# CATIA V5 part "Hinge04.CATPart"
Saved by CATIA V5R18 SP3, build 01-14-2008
Part number: Hinge 04
Bounding box of the stored display mesh (mm): x -47.5 to 47.5, y -15 to 15, z -22 to 22
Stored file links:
  E:\#00 CATIA V5 Movie\#03 CATIA V5 Data\#07 KIN\Balance Unit (1)\Hinge04.CATPart
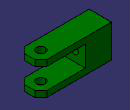
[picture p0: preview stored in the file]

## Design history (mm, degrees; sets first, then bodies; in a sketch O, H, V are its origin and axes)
Body1 (main body)
  Sketch1 on xy-plane, origin (0, 0, 0), H (1, 0, 0), V (0, 1, 0)
    line L1 (47.5, 7) -> (47.5, -7)
    line L2 (39.5, -15) -> (-47.5, -15)
    line L3 (-47.5, -15) -> (-47.5, 15)
    line L4 (-47.5, 15) -> (39.5, 15)
    point P1 (47.5, 15)
    point P2 (47.5, -15)
    point P4 (-47.5, 15)
    line L5 (47.5, 7) -> (39.5, 15)
    point P5 (47.5, 7)
    point P6 (39.5, 15)
    line L6 (47.5, -7) -> (39.5, -15)
    point P7 (47.5, -7)
    point P8 (39.5, -15)
    circle A1 centre (32.5, 0) radius 6
    point P9 (32.5, 0)
    distance P1 P2 = 30
    distance P4 P1 = 95
    distance P5 P1 = 8
    distance P6 P1 = 8
    distance P7 P2 = 8 {= Sketch1.distance(P5 P1)}
    distance P8 P2 = 8 {= Sketch1.distance(P6 P1)}
    distance P9 L3 = 80
    radius A1 = 6
    vertical: L1 V, L3 V
    horizontal: L2 H, L4 H
    equidistance: L1 L3 O, L2 L4 O
    coincidence: L1 P1, L4 P1, L1 P2, L2 P2, P9 H
  Pad1: profile Sketch1, direction (0, 0, 1), length 22, mirrored extent
  Sketch2 on face of Pad1 from Sketch1.L4, origin (0, 15, 0), H (-1, 0, 0), V (0, 0, 1)
    line L1 (-47.5, 14) -> (12.5, 14)
    line L2 (12.5, 14) -> (12.5, -14)
    line L3 (12.5, -14) -> (-47.5, -14)
    line L4 (-47.5, -14) -> (-47.5, 14)
    reference intersected line E1 through (-47.5, 0) direction (0, 1) from face of Pad1 from Sketch1.L1
    distance L2 L4 = 60
    length L4 = 28
    horizontal: L1 H, L3 H
    vertical: L2 V, L4 V
    coincidence: L4 E1
    symmetry: L1 L3 H
  Pocket1: profile Sketch2, direction (0, -1, 0), through (limit type 6)
  Sketch3 on face of Pad1 from Sketch1.L2, origin (-37.5, -15, 10), H (1, 0, 0), V (0, 0, 1)
    point P1 (0, 0)
    reference projected point E1 (0, 0) from Sketch4.P1
    coincidence: E1 P1
  Hole1: placed by Sketch3, at (-37.5, -15, 10) direction (0, 1, 0), diameter 4.917, depth 15, threaded "M6", thread diameter 6, thread depth 10, pitch 1
  Sketch4 on face of Pad1 from Sketch1.L2, origin (0, -15, 0), H (1, 0, 0), V (0, 0, 1)
    point P1 (-37.5, 10)
    point P2 (-37.5, -10)
    reference projected line E1 (-47.5, -22) -> (-47.5, 22) from edge [face of Pad1 from Sketch1.L2 | face of Pad1 from Sketch1.L3]
    distance P1 E1 = 10
    distance P1 P2 = 20
    symmetry: P1 P2 H
  UserPattern1: of Hole1, copies 2, at the points of Sketch4
  Sketch5 on face of Pad1 from Sketch1.L3, origin (-47.5, 0, 0), H (0, 1, 0), V (0, 0, -1)
    point P1 (0, 0)
    reference projected point E1 (0, 0) from Sketch6.P1
    coincidence: E1 P1
  Hole2: placed by Sketch5, at (-47.5, 0, 0) direction (1, 0, 0), diameter 10.647, through (limit type 6), threaded "M12x1.25", thread diameter 12, thread depth 10, pitch 1.25
  Sketch6 on face of Pad1 from Sketch1.L3, origin (-47.5, 0, 0), H (0, -1, 0), V (0, 0, 1)
    point P1 (0, 0)
    coincidence: P1 O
